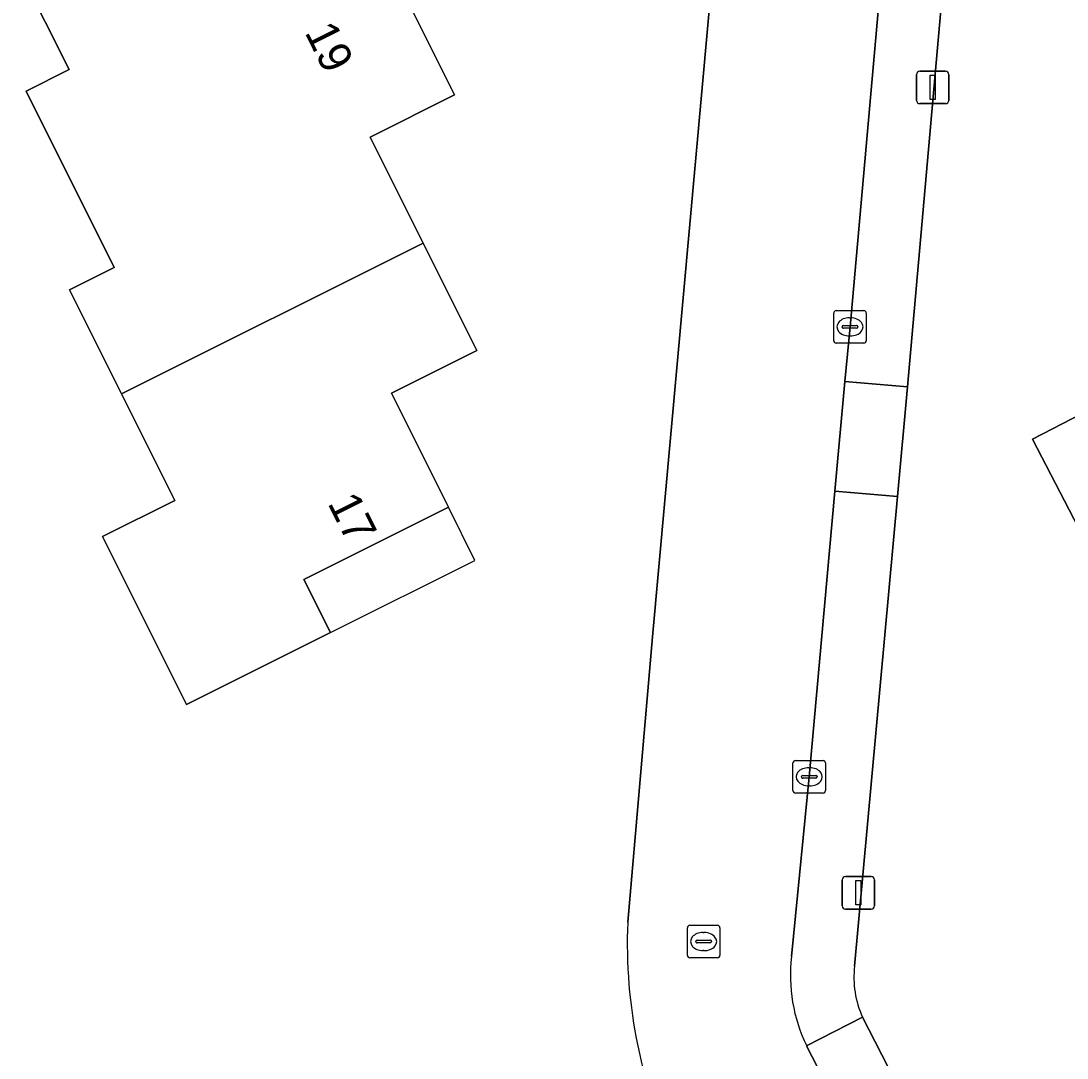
# Model space of a CAD drawing. Extents: x 162722 to 165104, y 384719 to 386284.
# Drawn here: x 163856.43 to 163888.6, y 385119.85 to 385151.76 of the extents above; entities that cross this region are included whole.
import ezdxf

# ---------------------------------------------------------------- set-up
doc = ezdxf.new("R2010")
doc.units = 0
for name, color, linetype in [('IMGEO_Erf', 7, 'Continuous'), ('IMGEO_Kolk', 7, 'Continuous'), ('IMGEO_Lichtmast', 7, 'Continuous'), ('IMGEO_Pand', 7, 'Continuous'), ('IMGEO_Pand_nummerreeks', 7, 'Continuous'), ('IMGEO_Pand_overbouw', 7, 'Continuous'), ('IMGEO_Rijbaan_lokaal_open', 7, 'Continuous'), ('IMGEO_Rioolput', 7, 'Continuous'), ('IMGEO_Voetpad_open', 7, 'Continuous')]:
    doc.layers.add(name, color=color, linetype=linetype)

msp = doc.modelspace()

# ---------------------------------------------------------------- linework, layer by layer
at = {"layer": 'IMGEO_Erf'}
for points in [[(163875.09, 385124.032), (163875.847, 385132.818), (163880.395, 385183.052)], [(163887.467, 385182.077), (163886.089, 385167.412), (163885.6, 385162.073), (163883.691, 385140.51), (163883.387, 385137.136), (163882.068, 385122.686)], [(163867.036, 385154.958), (163869.766, 385149.491), (163867.165, 385148.192), (163868.796, 385144.926), (163870.447, 385141.619), (163867.823, 385140.309), (163869.574, 385136.804), (163865.125, 385134.583), (163865.942, 385132.946), (163861.513, 385130.734), (163858.935, 385135.897), (163861.158, 385137.007), (163859.516, 385140.294), (163857.921, 385143.489), (163859.298, 385144.177), (163856.586, 385149.607), (163857.905, 385150.266), (163856.425, 385153.23)], [(163890.648, 385132.902), (163887.541, 385138.892), (163891.8, 385141.101)], [(163882.314, 385121.11), (163885.455, 385114.979), (163893.028, 385100.308), (163888.495, 385097.974), (163897.601, 385079.99), (163902.096, 385082.296), (163906.672, 385073.409), (163906.693, 385073.366), (163915.816, 385055.107), (163938.946, 385066.833)]]:
    msp.add_lwpolyline(points, dxfattribs=at)
for centre, radius, start, end in [((163890.68, 385123.38), 15.604, 177.6045, 205.7007), ((163885.011, 385122.338), 2.964, 173.2605, 204.4831)]:
    msp.add_arc(centre, radius, start, end, dxfattribs=at)
at = {"layer": 'IMGEO_Kolk'}
for p, q in [((163881.425, 385141.925), (163881.425, 385142.777)), ((163881.5, 385142.851), (163882.352, 385142.851)), ((163882.426, 385142.777), (163882.426, 385141.925)), ((163881.727, 385142.394), (163882.125, 385142.394)), ((163881.913, 385142.631), (163881.938, 385142.631)), ((163881.684, 385142.345), (163881.684, 385142.357)), ((163882.122, 385142.308), (163881.724, 385142.308)), ((163881.936, 385142.071), (163881.911, 385142.071)), ((163882.168, 385142.357), (163882.168, 385142.345)), ((163882.352, 385141.851), (163881.5, 385141.851)), ((163880.172, 385128.082), (163880.172, 385128.934)), ((163880.247, 385129.008), (163881.099, 385129.008)), ((163881.173, 385128.934), (163881.173, 385128.082)), ((163880.474, 385128.551), (163880.872, 385128.551)), ((163880.66, 385128.788), (163880.685, 385128.788)), ((163880.431, 385128.502), (163880.431, 385128.514)), ((163880.869, 385128.465), (163880.471, 385128.465)), ((163880.683, 385128.228), (163880.658, 385128.228)), ((163880.915, 385128.514), (163880.915, 385128.502)), ((163881.099, 385128.008), (163880.247, 385128.008))]:
    msp.add_line(p, q, dxfattribs=at)
for points in [[(163881.425, 385141.925), (163881.425, 385142.777)], [(163881.5, 385142.851), (163882.352, 385142.851)], [(163882.426, 385142.777), (163882.426, 385141.925)], [(163882.352, 385141.851), (163881.5, 385141.851)], [(163880.172, 385128.082), (163880.172, 385128.934)], [(163880.247, 385129.008), (163881.099, 385129.008)], [(163881.173, 385128.934), (163881.173, 385128.082)], [(163881.099, 385128.008), (163880.247, 385128.008)]]:
    msp.add_lwpolyline(points, dxfattribs=at)
for centre, radius, start, end in [((163881.502, 385142.775), 0.0765, 91.552, 178.448), ((163881.502, 385142.775), 0.0765, 91.552, 178.448), ((163882.35, 385142.775), 0.0765, 1.552, 88.448), ((163882.35, 385142.775), 0.0765, 1.552, 88.448), ((163881.724, 385142.354), 0.0403, 85.8775, 175.7526), ((163882.129, 385142.356), 0.0386, 1.7309, 96.639), ((163881.721, 385142.344), 0.0366, 178.938, 274.7102), ((163882.125, 385142.351), 0.043, 264.8664, 352.4533), ((163881.502, 385141.927), 0.0765, 181.552, 268.448), ((163881.502, 385141.927), 0.0765, 181.552, 268.448), ((163882.35, 385141.927), 0.0765, 271.552, 358.448), ((163882.35, 385141.927), 0.0765, 271.552, 358.448), ((163880.249, 385128.932), 0.0765, 91.552, 178.448), ((163880.249, 385128.932), 0.0765, 91.552, 178.448), ((163881.097, 385128.932), 0.0765, 1.552, 88.448), ((163881.097, 385128.932), 0.0765, 1.552, 88.448), ((163880.471, 385128.511), 0.0403, 85.8775, 175.7526), ((163880.876, 385128.513), 0.0386, 1.7309, 96.639), ((163880.468, 385128.501), 0.0366, 178.938, 274.7102), ((163880.872, 385128.508), 0.043, 264.8664, 352.4533), ((163880.249, 385128.084), 0.0765, 181.552, 268.448), ((163880.249, 385128.084), 0.0765, 181.552, 268.448), ((163881.097, 385128.084), 0.0765, 271.552, 358.448), ((163881.097, 385128.084), 0.0765, 271.552, 358.448)]:
    msp.add_arc(centre, radius, start, end, dxfattribs=at)
for centre, major_axis, ratio, start_param, end_param in [((163881.912, 385142.351), (-0.387, 0.002), 0.722429, 4.712389, 7.853982), ((163881.937, 385142.351), (-0.39, 0.002), 0.717154, 1.570796, 4.712389), ((163880.659, 385128.508), (-0.387, 0.002), 0.722429, 4.712389, 7.853982), ((163880.684, 385128.508), (-0.39, 0.002), 0.717154, 1.570796, 4.712389)]:
    msp.add_ellipse(centre, major_axis=major_axis, ratio=ratio, start_param=start_param, end_param=end_param, dxfattribs=at)
at = {"layer": 'IMGEO_Lichtmast'}
for p, q in [((163883.974, 385149.319), (163883.974, 385150.119)), ((163883.974, 385150.119), (163883.974, 385149.319)), ((163884.074, 385150.219), (163884.864, 385150.219)), ((163884.864, 385150.219), (163884.074, 385150.219)), ((163884.964, 385150.119), (163884.964, 385149.319)), ((163884.964, 385149.319), (163884.964, 385150.119)), ((163884.864, 385149.219), (163884.074, 385149.219)), ((163884.074, 385149.219), (163884.864, 385149.219)), ((163881.69, 385124.54), (163881.69, 385125.34)), ((163881.69, 385125.34), (163881.69, 385124.54)), ((163881.79, 385125.44), (163882.58, 385125.44)), ((163882.58, 385125.44), (163881.79, 385125.44)), ((163882.68, 385125.34), (163882.68, 385124.54)), ((163882.68, 385124.54), (163882.68, 385125.34)), ((163882.58, 385124.44), (163881.79, 385124.44)), ((163881.79, 385124.44), (163882.58, 385124.44))]:
    msp.add_line(p, q, dxfattribs=at)
for points in [[(163884.394, 385150.094), (163884.544, 385150.094), (163884.544, 385149.344), (163884.394, 385149.344), (163884.394, 385150.094)], [(163882.11, 385125.315), (163882.26, 385125.315), (163882.26, 385124.565), (163882.11, 385124.565), (163882.11, 385125.315)]]:
    msp.add_lwpolyline(points, dxfattribs=at)
for centre, start, end in [((163884.074, 385150.119), 90, 180), ((163884.074, 385150.119), 90, 180), ((163884.864, 385150.119), 0, 90), ((163884.864, 385150.119), 360, 90), ((163884.074, 385149.319), 180, 270), ((163884.074, 385149.319), 180, 270), ((163884.864, 385149.319), 270, 0), ((163884.864, 385149.319), 270, 0), ((163881.79, 385125.34), 90, 180), ((163881.79, 385125.34), 90, 180), ((163882.58, 385125.34), 0, 90), ((163882.58, 385125.34), 360, 90), ((163881.79, 385124.54), 180, 270), ((163881.79, 385124.54), 180, 270), ((163882.58, 385124.54), 270, 0), ((163882.58, 385124.54), 270, 0)]:
    msp.add_arc(centre, 0.1, start, end, dxfattribs=at)
at = {"layer": 'IMGEO_Pand'}
for points in [[(163869.766, 385149.491), (163867.036, 385154.958), (163862.181, 385152.533), (163860.753, 385155.392), (163857.694, 385153.864), (163856.425, 385153.23), (163857.905, 385150.266), (163856.586, 385149.607), (163859.298, 385144.177), (163857.921, 385143.489), (163859.516, 385140.294), (163868.796, 385144.926), (163867.165, 385148.192)], [(163902.091, 385141.966), (163898.722, 385148.46), (163897.958, 385149.932), (163892.29, 385150.271), (163891.973, 385144.959), (163893.513, 385141.989), (163891.8, 385141.101), (163887.541, 385138.892), (163890.648, 385132.902), (163900.198, 385137.859), (163898.921, 385140.321)], [(163867.823, 385140.309), (163870.447, 385141.619), (163868.796, 385144.926), (163859.516, 385140.294), (163861.158, 385137.007), (163858.935, 385135.897), (163861.513, 385130.734), (163865.942, 385132.946), (163865.125, 385134.583), (163869.574, 385136.804)]]:
    msp.add_lwpolyline(points, close=True, dxfattribs=at)
at = {"layer": 'IMGEO_Pand_overbouw'}
msp.add_lwpolyline([(163870.391, 385135.167), (163869.574, 385136.804), (163865.125, 385134.583), (163865.942, 385132.946)], close=True, dxfattribs=at)
at = {"layer": 'IMGEO_Rijbaan_lokaal_open'}
for points in [[(163879.917, 385185.913), (163880.235, 385184.011), (163880.395, 385183.052), (163875.847, 385132.818), (163875.09, 385124.032)], [(163880.673, 385128.508), (163881.456, 385137.298), (163881.772, 385140.671), (163881.926, 385142.351), (163883.129, 385155.885), (163883.667, 385162.254), (163884.19, 385167.579), (163885.467, 385181.214), (163885.575, 385182.33)], [(163880.129, 385122.974), (163880.673, 385128.508)], [(163886.395, 385108.759), (163886.141, 385109.315), (163883.749, 385114.101), (163880.593, 385120.234)]]:
    msp.add_lwpolyline(points, dxfattribs=at)
for centre, radius, start, end in [((163890.68, 385123.38), 15.604, 177.6045, 205.7007), ((163884.953, 385122.382), 4.86, 172.9983, 206.2246)]:
    msp.add_arc(centre, radius, start, end, dxfattribs=at)
at = {"layer": 'IMGEO_Rioolput'}
for p, q in [((163876.923, 385123.013), (163876.923, 385123.865)), ((163876.998, 385123.939), (163877.85, 385123.939)), ((163877.411, 385123.719), (163877.436, 385123.719)), ((163877.924, 385123.865), (163877.924, 385123.013)), ((163877.182, 385123.433), (163877.182, 385123.445)), ((163877.62, 385123.396), (163877.222, 385123.396)), ((163877.225, 385123.482), (163877.623, 385123.482)), ((163877.666, 385123.445), (163877.666, 385123.433)), ((163877.434, 385123.159), (163877.409, 385123.159)), ((163877.85, 385122.939), (163876.998, 385122.939))]:
    msp.add_line(p, q, dxfattribs=at)
for points in [[(163876.923, 385123.013), (163876.923, 385123.865)], [(163876.998, 385123.939), (163877.85, 385123.939)], [(163877.924, 385123.865), (163877.924, 385123.013)], [(163877.85, 385122.939), (163876.998, 385122.939)]]:
    msp.add_lwpolyline(points, dxfattribs=at)
for centre, radius, start, end in [((163877, 385123.863), 0.0765, 91.552, 178.448), ((163877, 385123.863), 0.0765, 91.552, 178.448), ((163877.848, 385123.863), 0.0765, 1.552, 88.448), ((163877.848, 385123.863), 0.0765, 1.552, 88.448), ((163877.222, 385123.442), 0.0403, 85.8775, 175.7526), ((163877.219, 385123.432), 0.0366, 178.938, 274.7102), ((163877.623, 385123.439), 0.043, 264.8664, 352.4533), ((163877.627, 385123.444), 0.0386, 1.7309, 96.639), ((163877, 385123.015), 0.0765, 181.552, 268.448), ((163877, 385123.015), 0.0765, 181.552, 268.448), ((163877.848, 385123.015), 0.0765, 271.552, 358.448), ((163877.848, 385123.015), 0.0765, 271.552, 358.448)]:
    msp.add_arc(centre, radius, start, end, dxfattribs=at)
for centre, major_axis, ratio, start_param, end_param in [((163877.41, 385123.439), (-0.387, 0.002), 0.722429, 4.712389, 7.853982), ((163877.435, 385123.439), (-0.39, 0.002), 0.717154, 1.570796, 4.712389)]:
    msp.add_ellipse(centre, major_axis=major_axis, ratio=ratio, start_param=start_param, end_param=end_param, dxfattribs=at)
at = {"layer": 'IMGEO_Voetpad_open'}
for points in [[(163883.667, 385162.254), (163883.129, 385155.885), (163881.926, 385142.351), (163881.772, 385140.671), (163883.691, 385140.51), (163885.6, 385162.073)], [(163881.772, 385140.671), (163881.456, 385137.298), (163883.387, 385137.136), (163883.691, 385140.51)], [(163880.593, 385120.234), (163883.749, 385114.101), (163885.455, 385114.979), (163882.314, 385121.11)]]:
    msp.add_lwpolyline(points, close=True, dxfattribs=at)
for points in [[(163882.068, 385122.686), (163883.387, 385137.136), (163881.456, 385137.298), (163880.673, 385128.508), (163880.129, 385122.974)], [(163880.593, 385120.234), (163882.314, 385121.11)]]:
    msp.add_lwpolyline(points, dxfattribs=at)
for centre, radius, start, end in [((163884.953, 385122.382), 4.86, 172.9983, 206.2246), ((163885.011, 385122.338), 2.964, 173.2605, 204.4831)]:
    msp.add_arc(centre, radius, start, end, dxfattribs=at)

# ---------------------------------------------------------------- texts
at = {"layer": 'IMGEO_Pand_nummerreeks'}
for s, rotation, p in [('19', 296.5335, (163865.138, 385151.417)), ('17', 296.5392, (163865.845, 385136.93))]:
    msp.add_text(s, height=1, rotation=rotation, dxfattribs=at).set_placement(p)

doc.saveas('drawing.dxf')
